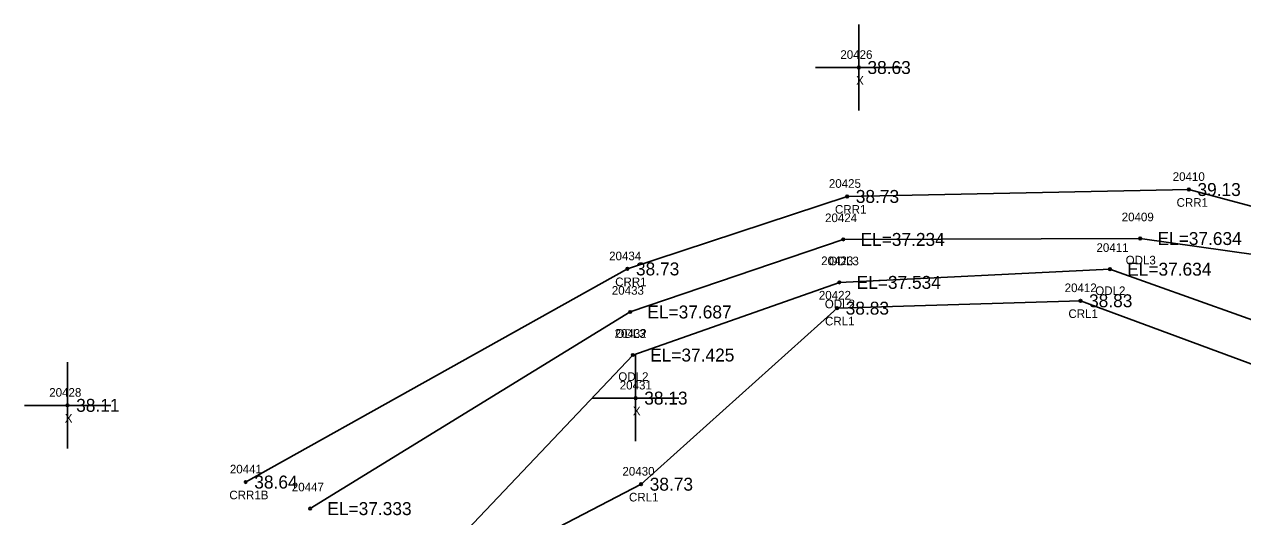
# Model space of a CAD drawing. Extents: x 2619569 to 2620117, y 784503 to 785150.
# Drawn here: x 2619577.9 to 2619719.1, y 784899.6 to 784956.7 of the extents above; entities that cross this region are included whole.
import ezdxf

# ---------------------------------------------------------------- set-up
doc = ezdxf.new("R2010")
doc.units = 0
for name, color, linetype in [('RD_EX_H2O', 7, 'Continuous'), ('RD_EX_H2O_txCode', 7, 'Continuous'), ('RD_EX_Misc', 7, 'Continuous'), ('RD_EX_Misc_txCode', 7, 'Continuous'), ('RD_EX_TX_H2O_ELEV', 7, 'Continuous'), ('RD_EX_TX_Misc_ELEV', 7, 'Continuous'), ('RD_SMD_Locator', 7, 'Continuous')]:
    doc.layers.add(name, color=color, linetype=linetype)

msp = doc.modelspace()

# ---------------------------------------------------------------- linework, layer by layer
at = {"layer": 'RD_EX_H2O'}
for points in [[(2619772.64, 784911.68), (2619752.83, 784926.84), (2619712.83, 784937.52), (2619673.24, 784936.72), (2619647.77, 784928.32), (2619603.54, 784903.62)], [(2619777.15, 784906.8), (2619751.24, 784925.62), (2619707.2, 784931.84), (2619672.79, 784931.74), (2619648.09, 784923.33), (2619611.01, 784900.54)], [(2619790.27, 784838.72), (2619782.87, 784866.71), (2619738.56, 784915.87), (2619703.69, 784928.29), (2619672.34, 784926.76), (2619648.41, 784918.34), (2619619.29, 784887.62)], [(2619773.83, 784850.15), (2619780.57, 784864.79), (2619733.81, 784912.21), (2619700.27, 784924.63), (2619672.07, 784923.77), (2619649.36, 784903.37), (2619624.57, 784890.48)]]:
    msp.add_lwpolyline(points, dxfattribs=at)
at = {"layer": 'RD_EX_Misc'}
for p, q in [((2619674.59, 784946.66), (2619674.59, 784956.66)), ((2619669.59, 784951.66), (2619679.59, 784951.66)), ((2619648.73, 784908.35), (2619648.73, 784918.35)), ((2619582.9, 784907.51), (2619582.9, 784917.51)), ((2619577.9, 784912.51), (2619587.9, 784912.51)), ((2619643.73, 784913.35), (2619653.73, 784913.35))]:
    msp.add_line(p, q, dxfattribs=at)
at = {"layer": 'RD_SMD_Locator'}
for centre in [(2619674.59, 784951.66), (2619673.24, 784936.72), (2619712.83, 784937.52), (2619672.79, 784931.74), (2619707.2, 784931.84), (2619647.77, 784928.32), (2619703.69, 784928.29), (2619672.34, 784926.76), (2619672.07, 784923.77), (2619700.27, 784924.63), (2619648.09, 784923.33), (2619648.41, 784918.34), (2619582.9, 784912.51), (2619648.73, 784913.35), (2619603.54, 784903.62), (2619649.36, 784903.37), (2619611.01, 784900.54)]:
    msp.add_circle(centre, 0.15, dxfattribs=at)

# ---------------------------------------------------------------- texts
at = {"layer": 'RD_EX_H2O_txCode'}
for s, p in [('20410', (2619710.96, 784938.52)), ('20425', (2619671.12, 784937.72)), ('CRR1', (2619711.41, 784935.52)), ('CRR1', (2619671.83, 784934.72)), ('20424', (2619670.68, 784933.74)), ('20409', (2619705.05, 784933.84)), ('20411', (2619702.13, 784930.29)), ('20434', (2619645.66, 784929.32)), ('20423', (2619670.23, 784928.76)), ('ODL3', (2619671.1, 784928.74)), ('ODL3', (2619705.51, 784928.84)), ('CRR1', (2619646.36, 784926.32)), ('20412', (2619698.44, 784925.63)), ('20433', (2619645.97, 784925.33)), ('20422', (2619669.96, 784924.77)), ('ODL2', (2619701.99, 784925.29)), ('ODL2', (2619670.65, 784923.76)), ('CRL1', (2619670.68, 784921.77)), ('CRL1', (2619698.88, 784922.63)), ('20432', (2619646.29, 784920.34)), ('ODL3', (2619646.4, 784920.33)), ('ODL2', (2619646.72, 784915.34)), ('20441', (2619601.71, 784904.62)), ('20430', (2619647.2, 784904.37)), ('CRR1B', (2619601.65, 784901.62)), ('20447', (2619608.89, 784902.54)), ('CRL1', (2619647.96, 784901.37))]:
    msp.add_text(s, height=1, dxfattribs=at).set_placement(p)
at = {"layer": 'RD_EX_Misc_txCode'}
for s, p in [('20426', (2619672.45, 784952.66)), ('X', (2619674.28, 784949.66)), ('20431', (2619646.89, 784914.35)), ('20428', (2619580.78, 784913.51)), ('X', (2619582.58, 784910.51)), ('X', (2619648.41, 784911.35))]:
    msp.add_text(s, height=1, dxfattribs=at).set_placement(p)
at = {"layer": 'RD_EX_TX_H2O_ELEV'}
for s, p in [('39.13', (2619713.83, 784936.77)), ('38.73', (2619674.24, 784935.97)), ('EL=37.234', (2619674.79, 784930.99)), ('EL=37.634', (2619709.2, 784931.09)), ('38.73', (2619648.77, 784927.57)), ('EL=37.634', (2619705.69, 784927.54)), ('EL=37.534', (2619674.34, 784926.01)), ('38.83', (2619701.27, 784923.88)), ('EL=37.687', (2619650.09, 784922.58)), ('38.83', (2619673.07, 784923.02)), ('EL=37.425', (2619650.41, 784917.59)), ('38.64', (2619604.54, 784902.87)), ('38.73', (2619650.36, 784902.62)), ('EL=37.333', (2619613.01, 784899.79))]:
    msp.add_text(s, height=1.5, dxfattribs=at).set_placement(p)
at = {"layer": 'RD_EX_TX_Misc_ELEV'}
for s, p in [('38.63', (2619675.59, 784950.91)), ('38.13', (2619649.73, 784912.6)), ('38.11', (2619583.9, 784911.76))]:
    msp.add_text(s, height=1.5, dxfattribs=at).set_placement(p)

doc.saveas('drawing.dxf')
